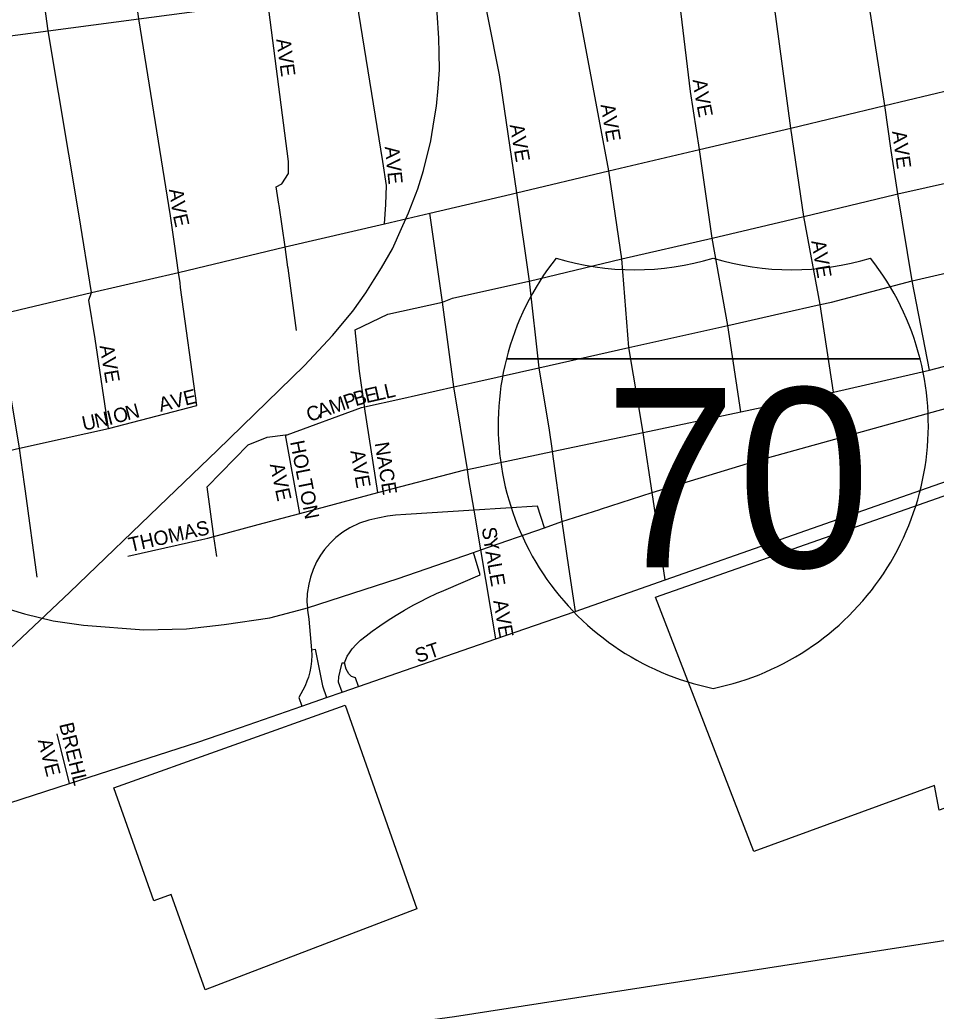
# Model space of a CAD drawing. Extents: x 0 to 34, y -6.2 to 22.
# Drawn here: x 4.825 to 5.43, y 16.806 to 17.461 of the extents above; entities that cross this region are included whole.
import ezdxf

# ---------------------------------------------------------------- set-up
doc = ezdxf.new("R2010")
doc.units = 0
for name, color, linetype in [('GM_X_City_Street', 7, 'Continuous'), ('GM_X_City_Street_Text', 7, 'Continuous'), ('GM_X_Corporation', 7, 'Continuous'), ('GM_X_Interchange_Ramps', 7, 'Continuous'), ('GM_X_Interstate_Route', 7, 'Continuous'), ('GM_X_Interstate_Shield', 7, 'Continuous'), ('GM_X_Rail_Line', 7, 'Continuous')]:
    doc.layers.add(name, color=color, linetype=linetype)

msp = doc.modelspace()

# ---------------------------------------------------------------- linework, layer by layer
at = {"layer": 'GM_X_City_Street'}
for points in [[(5.42525, 17.22968), (5.41386, 17.28871), (5.40433, 17.34625), (5.40006, 17.3747), (5.39578, 17.40462), (5.38186, 17.49365), (5.377, 17.53601), (5.3726, 17.57257), (5.3657, 17.61726), (5.34724, 17.71592), (5.33224, 17.8149), (5.32675, 17.84985)], [(5.36195, 17.21528), (5.35318, 17.27302), (5.34218, 17.33113), (5.3338, 17.38966), (5.31525, 17.52736), (5.3034, 17.60812), (5.28603, 17.70679), (5.27114, 17.80492), (5.26614, 17.84111)], [(5.30071, 17.20226), (5.29214, 17.25934), (5.28185, 17.31699), (5.2733, 17.37536), (5.26754, 17.41366), (5.26125, 17.46498), (5.25292, 17.51806), (5.24021, 17.59885), (5.22508, 17.69796), (5.22354, 17.70725), (5.21054, 17.79616), (5.2056, 17.83167)], [(5.25069, 17.09128), (5.24207, 17.14892), (5.23659, 17.18552), (5.23608, 17.18864), (5.22683, 17.24471), (5.22217, 17.30318), (5.21675, 17.33919), (5.21345, 17.36138), (5.18662, 17.50498), (5.1862, 17.5081), (5.17526, 17.58933), (5.16448, 17.68883), (5.15, 17.78671), (5.14362, 17.82263)], [(5.0833, 17.81357), (5.08811, 17.77802), (5.10258, 17.6794), (5.11521, 17.58052), (5.12628, 17.49915), (5.14112, 17.42484), (5.15246, 17.34675), (5.16101, 17.28855), (5.16721, 17.23134), (5.17402, 17.19009), (5.17587, 17.17805)], [(5.06532, 17.32636), (5.06631, 17.33919), (5.06664, 17.35168), (5.06417, 17.36747), (5.04591, 17.48059), (5.03345, 17.56811), (5.0194, 17.66717), (5.00476, 17.76584), (4.9999, 17.80139)], [(4.92669, 17.31319), (4.92411, 17.33163), (4.90319, 17.46174), (4.89075, 17.54645), (4.87732, 17.64607), (4.86258, 17.7445), (4.85833, 17.77958)], [(4.88317, 17.19122), (4.87429, 17.25041), (4.87002, 17.27589), (4.87182, 17.28098), (4.86376, 17.33163), (4.84318, 17.45382), (4.83191, 17.53751), (4.818, 17.63713), (4.8033, 17.73547), (4.79891, 17.77088)], [(4.99574, 17.33843), (4.99561, 17.33929), (4.99392, 17.35071), (4.99768, 17.3527), (5.00203, 17.35958), (5.00203, 17.36747), (4.98841, 17.473), (4.97581, 17.55936), (4.95788, 17.65811), (4.94519, 17.746), (4.94281, 17.75126), (4.93866, 17.75323), (4.93345, 17.75329), (4.93315, 17.75557), (4.93255, 17.75955)], [(4.71847, 17.43735), (4.78304, 17.44587), (4.84318, 17.45382), (4.90319, 17.46174), (4.98841, 17.473), (5.04591, 17.48059), (5.07541, 17.48449)], [(5.14909, 17.34597), (5.15246, 17.34675), (5.21345, 17.36138), (5.2733, 17.37536), (5.3338, 17.38966), (5.39578, 17.40462), (5.46943, 17.42205), (5.54456, 17.43964), (5.61411, 17.45591), (5.61792, 17.45684)], [(5.40267, 17.34585), (5.40433, 17.34625), (5.47913, 17.36302), (5.5541, 17.38094), (5.62282, 17.39755), (5.6255, 17.39818)], [(5.32779, 17.26733), (5.35318, 17.27302), (5.36059, 17.27475), (5.41386, 17.28871), (5.48817, 17.30598), (5.56281, 17.32357), (5.63203, 17.34067), (5.69299, 17.3546), (5.73133, 17.36335), (5.73922, 17.36533)], [(4.74852, 17.25172), (4.80984, 17.26619), (4.87182, 17.28098), (4.92936, 17.29414), (4.99976, 17.31125), (5.06532, 17.32636), (5.09525, 17.33343), (5.14909, 17.34597)], [(5.16058, 17.28846), (5.16101, 17.28855), (5.22217, 17.30318), (5.28185, 17.31699), (5.34218, 17.33113), (5.40267, 17.34585)], [(5.00169, 17.29719), (5.00163, 17.29767), (4.99976, 17.31125), (4.99574, 17.33843)], [(5.13899, 17.05233), (5.12905, 17.11107), (5.1246, 17.13734), (5.12117, 17.15762), (5.12009, 17.16426), (5.11126, 17.2188), (5.10363, 17.27458), (5.09525, 17.33343)], [(4.93076, 17.28441), (4.93035, 17.2874), (4.92936, 17.29414), (4.92669, 17.31319)], [(5.00735, 17.25592), (5.00169, 17.29719)], [(5.0461, 17.25638), (5.06763, 17.26669), (5.10363, 17.27458), (5.11021, 17.27721), (5.16058, 17.28846)], [(4.94137, 17.20651), (4.93076, 17.28441)], [(5.07613, 17.21093), (5.11126, 17.2188), (5.1269, 17.22231), (5.16721, 17.23134), (5.22683, 17.24471), (5.29214, 17.25934), (5.32779, 17.26733)], [(5.06106, 17.14893), (5.05223, 17.20558), (5.05211, 17.20631), (5.04896, 17.22906), (5.0461, 17.25638)], [(4.82824, 17.14988), (4.8276, 17.15456), (4.82431, 17.17823), (4.81392, 17.2406)], [(4.98197, 17.12774), (5.00938, 17.13508), (5.06106, 17.14893), (5.11845, 17.16391), (5.12009, 17.16426), (5.17618, 17.17601), (5.23608, 17.18864), (5.30071, 17.20226), (5.36195, 17.21528), (5.42525, 17.22968), (5.4531, 17.23699)], [(4.94823, 17.15274), (4.97544, 17.18035), (4.98784, 17.18555), (4.99997, 17.18702), (5.00104, 17.18715), (5.05024, 17.20513), (5.05223, 17.20558), (5.07613, 17.21093)], [(4.72945, 17.1567), (4.76118, 17.1636), (4.82431, 17.17823), (4.85324, 17.18465), (4.88317, 17.19122), (4.94137, 17.20651)], [(5.03731, 17.01708), (5.04817, 17.02085), (5.08438, 17.03339), (5.13899, 17.05233), (5.19118, 17.07042), (5.25069, 17.09128), (5.49169, 17.17576), (5.57935, 17.20648)], [(5.00938, 17.13508), (4.99997, 17.18702)], [(5.17587, 17.17805), (5.17618, 17.17601), (5.1825, 17.1298), (5.18689, 17.09976)], [(4.95458, 17.10672), (4.95276, 17.11991), (4.94823, 17.15274)], [(4.83604, 17.09316), (4.82824, 17.14988)], [(4.89578, 17.10702), (4.94481, 17.11796), (4.94873, 17.11883), (4.95276, 17.11991), (4.98197, 17.12774)], [(5.18689, 17.09976), (5.19118, 17.07042)], [(4.80958, 16.94143), (4.85729, 16.95678), (4.94203, 16.98405), (4.97019, 16.99381), (5.01085, 17.00791), (5.02715, 17.01356), (5.03731, 17.01708)], [(4.85729, 16.95678), (4.84928, 16.9896)]]:
    msp.add_lwpolyline(points, dxfattribs=at)
at = {"layer": 'GM_X_Corporation'}
for points in [[(5.48815, 17.16556), (5.52656, 16.97299), (5.43174, 16.93918), (5.4285, 16.95541), (5.30924, 16.912), (5.24427, 17.07977), (5.48815, 17.16556)], [(5.03935, 17.00861), (5.08668, 16.87398), (4.94691, 16.82064), (4.92453, 16.88359), (4.91316, 16.87938), (4.88667, 16.95402), (5.03935, 17.00861)], [(4.70782, 16.75228), (4.9482, 16.78064), (5.11165, 16.80294), (5.45456, 16.85626), (5.4745, 16.64057), (5.5641, 16.62943), (5.60017, 16.43531), (5.64172, 16.4323), (5.65365, 16.59687), (5.68191, 16.60151), (5.6688, 16.65291), (5.81758, 16.67223), (5.85861, 16.51137), (5.91469, 16.51071), (5.92741, 16.41722), (6.00509, 16.42105), (6.01527, 16.37356), (5.91783, 16.3717), (5.91284, 16.41628), (5.6308, 16.42713), (5.61361, 16.26509)]]:
    msp.add_lwpolyline(points, dxfattribs=at)
at = {"layer": 'GM_X_Interchange_Ramps'}
for points in [[(5.17098, 17.12575), (5.1664, 17.14003), (5.1246, 17.13734), (5.07943, 17.13444), (5.07271, 17.13397), (5.06742, 17.1333), (5.06104, 17.13212), (5.05506, 17.13064), (5.04894, 17.12865), (5.04258, 17.1257), (5.03782, 17.12278), (5.03314, 17.11916), (5.02942, 17.11563), (5.02573, 17.11135), (5.02304, 17.10755), (5.02049, 17.10316), (5.01817, 17.09812), (5.01643, 17.09309), (5.0153, 17.08853), (5.0144, 17.08233), (5.01419, 17.07687), (5.01443, 17.07273), (5.01451, 17.07137), (5.0155, 17.06539), (5.01716, 17.04503), (5.01729, 17.04161), (5.01714, 17.03771), (5.01671, 17.03406), (5.01607, 17.03066), (5.01511, 17.02706), (5.01417, 17.02431), (5.01291, 17.02123), (5.0115, 17.01839), (5.00884, 17.01372), (5.01085, 17.00791)], [(5.04817, 17.02085), (5.04622, 17.0265), (5.04357, 17.02749), (5.04177, 17.02921), (5.04015, 17.03238), (5.03903, 17.03658), (5.04074, 17.04086), (5.04228, 17.04318), (5.044, 17.04575), (5.04659, 17.04864), (5.04954, 17.05144), (5.05321, 17.05435), (5.05721, 17.05735), (5.06237, 17.06104), (5.06772, 17.06464), (5.07313, 17.06808), (5.07853, 17.0713), (5.08421, 17.07448), (5.08872, 17.07686), (5.09423, 17.07959), (5.0998, 17.08218), (5.10448, 17.08422), (5.12854, 17.09457), (5.12409, 17.10933)], [(5.01716, 17.04503), (5.0195, 17.04552), (5.02443, 17.0214), (5.02715, 17.01356)], [(5.03731, 17.01708), (5.03496, 17.02384), (5.03526, 17.02715), (5.03603, 17.03101), (5.03732, 17.03658), (5.03903, 17.03658)]]:
    msp.add_lwpolyline(points, dxfattribs=at)
at = {"layer": 'GM_X_Interstate_Route'}
for points in [[(5.3104, 17.16956), (5.4454, 17.20706), (5.53799, 17.22569), (5.57483, 17.2325)], [(5.20802, 17.13801), (5.24207, 17.14892), (5.30502, 17.16806), (5.3104, 17.16956)], [(5.01218, 17.07214), (5.01443, 17.07273), (5.07441, 17.09225), (5.12409, 17.10933), (5.12905, 17.11107), (5.17098, 17.12575), (5.1825, 17.1298), (5.20754, 17.13785), (5.20802, 17.13801)], [(4.75357, 17.09804), (4.77219, 17.08896), (4.80849, 17.07448), (4.82761, 17.06896), (4.84667, 17.06431), (4.86651, 17.06134), (4.90643, 17.05836), (4.93471, 17.05886), (4.9595, 17.06183), (4.98975, 17.0663), (5.01218, 17.07214)]]:
    msp.add_lwpolyline(points, dxfattribs=at)
at = {"layer": 'GM_X_Interstate_Shield'}
for p, q in [((5.14583, 17.23716), (5.41909, 17.23716)), ((5.41909, 17.23716), (5.14583, 17.23716)), ((5.41909, 17.23716), (5.14583, 17.23716))]:
    msp.add_line(p, q, dxfattribs=at)
for centre, start, end in [((5.31797, 17.19363), 141.66896, 165.80665), ((5.23057, 17.47356), 253.00908, 286.99093), ((5.33435, 17.47356), 253.00908, 286.99093), ((5.24695, 17.19363), 14.19335, 38.33104), ((5.31797, 17.19363), 165.80665, 258.46304), ((5.24695, 17.19363), 281.53696, 14.19335)]:
    msp.add_arc(centre, 0.17756, start, end, dxfattribs=at)
at = {"layer": 'GM_X_Rail_Line'}
for points in [[(5.07955, 17.32965), (5.08132, 17.33369), (5.08736, 17.34946), (5.09117, 17.36159), (5.09599, 17.38112), (5.09826, 17.39515), (5.09964, 17.4041), (5.10082, 17.41606), (5.10164, 17.42815), (5.10155, 17.43932), (5.10133, 17.44889), (5.10018, 17.46568), (5.09719, 17.49148), (5.08504, 17.57262)], [(4.77838, 17.00846), (4.85756, 17.08323), (4.92206, 17.14525), (4.95497, 17.1767), (5.01262, 17.23276), (5.03112, 17.25256), (5.04436, 17.26872), (5.05296, 17.28081), (5.05863, 17.28954), (5.06344, 17.29726), (5.07057, 17.30978), (5.07669, 17.32332), (5.07955, 17.32965)]]:
    msp.add_lwpolyline(points, dxfattribs=at)

# ---------------------------------------------------------------- texts
at = {"layer": 'GM_X_City_Street_Text'}
for s, rotation, p in [('AVE', 277.85664, (4.99384, 17.44819)), ('A', 277.36358, (5.26885, 17.42144)), ('V', 280.34787, (5.27, 17.41264)), ('AVE', 279.78342, (5.208, 17.40492)), ('E', 280.77669, (5.27152, 17.40437)), ('AVE', 279.77737, (5.148, 17.39159)), ('AVE', 277.85561, (5.4005, 17.38736)), ('AVE', 275.91546, (5.06552, 17.37722)), ('A', 278.51025, (4.92301, 17.34902)), ('V', 278.50211, (4.92424, 17.34078)), ('E', 282.70658, (4.92562, 17.3318)), ('AVE', 279.78468, (5.34716, 17.31492)), ('AVE', 279.78468, (4.87716, 17.24575)), ('AVE', 14.03624, (4.91748, 17.20218)), ('B', 15.86866, (5.04631, 17.20591)), ('E', 12.92294, (5.05339, 17.20793)), ('L', 12.72435, (5.05988, 17.20942)), ('L', 12.72435, (5.06639, 17.21089)), ('M', 18.80873, (5.03065, 17.20058)), ('P', 18.80698, (5.04012, 17.2038)), ('I', 14.42386, (4.88343, 17.19333)), ('O', 15.0234, (4.88758, 17.1944)), ('N', 15.05898, (4.89563, 17.19656)), ('C', 18.81896, (5.01566, 17.19547)), ('A', 18.8012, (5.02276, 17.19789)), ('U', 11.95281, (4.86671, 17.1897)), ('N', 12.53504, (4.87497, 17.19145)), ('HOLTON', 281.1109, (5.00299, 17.18246)), ('NACE', 279.21213, (5.05883, 17.18157)), ('AVE', 279.78342, (5.04278, 17.17632)), ('AVE', 282.09583, (4.98955, 17.16741)), ('THOMAS', 12.6341, (4.89752, 17.10969)), ('S', 277.12166, (5.12968, 17.12567)), ('YALE', 279.86481, (5.1305, 17.11826)), ('AVE', 279.78468, (5.13716, 17.07742)), ('ST', 18.4262, (5.08735, 17.03631)), ('BREHL', 283.7376, (4.85047, 16.99587)), ('AVE', 284.03625, (4.83633, 16.98527))]:
    msp.add_text(s, height=0.00947, rotation=rotation, dxfattribs=at).set_placement(p)
at = {"layer": 'GM_X_Interstate_Shield'}
msp.add_text('70', height=0.118371, dxfattribs=at).set_placement((5.21025, 17.09956))

doc.saveas('drawing.dxf')
